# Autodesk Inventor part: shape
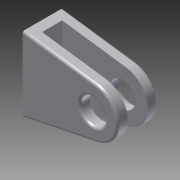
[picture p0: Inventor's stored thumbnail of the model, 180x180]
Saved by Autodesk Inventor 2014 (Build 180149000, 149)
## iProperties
Created: 2009-11
Part Number: shape
Document SubType Name: Modeling
Designer: pokornp
Density: 1 g/cm^3
Mass: 9216 g
Surface Area: 5440 cm^2
Volume: 9216 cm^3
Material: Generic
Appearance: Default
Author: pokornp
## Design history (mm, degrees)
sketch "Sketch1"
  geometry: L1 (0, 0)-(0, -160); L2 (0, -160)-(400, -160); L3 (400, -160)-(400, -120); L4 (400, -120)-(40, -120); L5 (40, -120)-(40, -40); L6 (40, -40)-(400, -40); L7 (400, -40)-(400, 0); L8 (400, 0)-(0, 0)
  constraints: 16 end point, 6 parallel, 1 perpendicular, 1 vertical, 1 vertical alignment
  dimensions: "w" = 160 distance of L1.start L1.end; "d1" = 80 distance of L4.end L5.end (= 0.5 x w); "d2" = 40 distance of L2.end L3.end (= 0.25 x w); "d3" = 40 distance between parallel lines of L1 L5 (= 0.25 x w); "d4" = 400 distance of L1.end L2.end (= 2.5 x w)
extrude "Extrusion1" new body sketch "Sketch1" distance "d5" = 320 (= 2 x w); taper "d6" = 0 deg
hole "Hole1" diameter "d9" = 100; stored, may be unused: countersink angle "d13" = 90 deg, drill point angle "d15" = 118 deg; dims "d7" = 120, "d8" = 150, "d10" = 6, "d11" = 4, "d12" = 2, "d14" = 8
fillet "Fillet1" dims "d16" = 50
fillet "Fillet2" dims "d17" = 10
sketch "Sketch2"
  geometry: L1 (0, 0)-(0, -300) reference; L2 (0, -300)-(293.656, -259.831); L3 (0, 0)-(300.154, -61.275); A1 r 100.761 centre (280, -160) between (293.656, -259.831) and (300.154, -61.275); 1 further point
  constraints: 4 end point, 2 point on circle, 2 tangent, 1 centre point
extrude "Extrusion2" sketch "Sketch2" stored distance "d18" = 320 (= 2 x w); taper "d19" = 0 deg
fillet "Fillet3" dims "d20" = 10
fillet "Fillet5" dims "d22" = 5
body "Solid1"
